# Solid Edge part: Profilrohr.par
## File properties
Username: bmolnar
Dokumentum tartalom típus: 0
Author: bmolnar
Last saved by: bmolnar
Revision: 79
Sűrűség: 0,000 kg/m^3
Pontosság: 0,990
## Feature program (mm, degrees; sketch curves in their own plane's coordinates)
base feature "unnamed BaseFeature 1"
thread "unnamed Thread 1"
thread "Menet_4"  ThreadDepth = 9.3 mm
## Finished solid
Body 1: solid body, 177 faces, 454 edges, 298 vertices.
  Faces by surface: plane 102, cylinder 65, cone 6, torus 4
  Edges by curve: line 308, circle 136, curve on surface 7, spline 2, intersection 1
Bounding box of the edges (mm; curved faces can reach further): 124.000 x 131.000 x 76.000, from (-62, -62, 0) to (62, 69, 76).
Cylindrical faces by radius (mm): R0.2 x24, R2.625 x2, R5.5 x8, R5.7225 x4, R8.6 x16, R50 x1, R50.85 x2, R51.1 x2, R53.1 x2, R84 x4
Conical faces (half-angle, radius in mm at the cone's reference point): 30 deg R50.325 x2, 30 deg R51.283 x2, 45 deg R6.0725 x2
Toroidal faces (ring radius, tube radius in mm): R52.9 r0.2 x4
Planar faces by outward normal: +x 9, +y 11, +z 8, -x 9, -y 9, -z 8, oblique 48
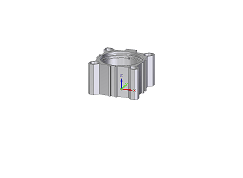
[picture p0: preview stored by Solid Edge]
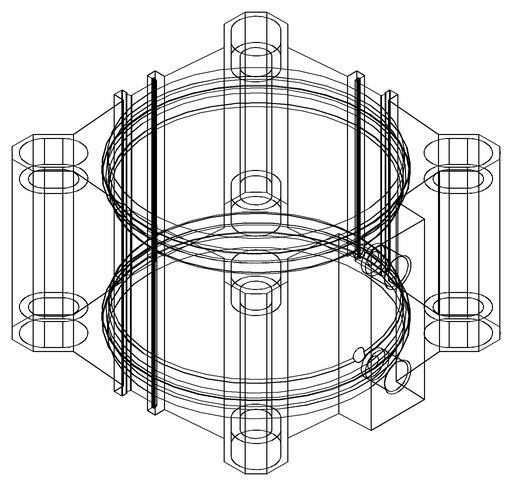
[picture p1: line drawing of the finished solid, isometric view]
